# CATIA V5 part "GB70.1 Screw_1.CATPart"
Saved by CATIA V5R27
Part number: 螺钉_PowerCopy_1
Bounding box of the stored display mesh (mm): x -8 to 8, y -8 to 8, z -10 to 25
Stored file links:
  E:\资料\Catia超级副本\GB 70.1螺钉_带弹垫平垫\GB70.1 Screw_1.CATPart
  E:\资料\Catia超级副本\GB70.1 螺钉\DesignTable.xlsx
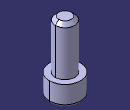
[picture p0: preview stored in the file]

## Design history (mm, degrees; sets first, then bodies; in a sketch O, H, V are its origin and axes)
Parameters
  `圆柱头直径` = 16 mm {design table}
  `圆柱头厚度` = 10 mm {design table}
  s = 8 mm {design table}
  t = 5 mm {design table}
  v = 1 mm {design table}
  b = 1.8 mm {design table}
  `公称直径` = 10 mm {design table}
  `螺钉长度` = 25 mm {design table}
AxisSystem1: origin (0, 0, 0), X (1, 0, 0), Y (0, 1, 0), Z (0, 0, 1)
Set1 "定位元素"
  Plane1: type Normal, Curve Line1, RefPoint Point1, Ratio 0
  Point1: (0, 0, 0), in AxisSystem1
Body1 (main body)
  Sketch1 on Plane1, origin (0, 0, 0), H (1, 0, 0), V (0, 1, 0)
    circle A1 centre (0, 0) radius 8
    radius A1 = 8 {= `圆柱头直径` /2}
  Pad1: profile Sketch1, direction (0, 0, -1), length 10 {= `圆柱头厚度`}
  Fillet1: radius 1 {= v}, on end face of Pad1
  Sketch2 on Plane1, origin (0, 0, 0), H (1, 0, 0), V (0, 1, 0)
    circle A1 centre (0, 0) radius 5
    radius A1 = 5 {= `公称直径` /2}
  Pad2: profile Sketch2, direction (0, 0, 1), length 25 {= `螺钉长度`}
  Chamfer1: length 1.8 {= b}, angle 45, on end face of Pad2
  Set2
    Line1: type PtDir, RefPoint Point1, Direction (0, 0, 1), Start 0, End 20
  Sketch3 on end face of Pad1, origin (0, 0, -10), H (1, 0, 0), V (0, -1, 0)
    point P1 (0, 0)
    point P2 (4, 0)
    construction circle A1 centre (0, 0) radius 4.6188
    construction circle A2 centre (0, 0) radius 4
    point P3 (4, -2.3094)
    point P4 (4, 2.3094)
    point P5 (0, 4.6188)
    point P6 (-4, 2.3094)
    point P7 (-4, -2.3094)
    point P8 (0, -4.6188)
    line L1 (4, -2.3094) -> (4, 2.3094)
    line L2 (4, 2.3094) -> (0, 4.6188)
    line L3 (0, 4.6188) -> (-4, 2.3094)
    line L4 (-4, 2.3094) -> (-4, -2.3094)
    line L5 (-4, -2.3094) -> (0, -4.6188)
    line L6 (0, -4.6188) -> (4, -2.3094)
    construction line L7 (0, 0) -> (4, 0)
    reference projected point E1 (0, 0) from axis of face of Pad1 from Sketch1.A1
    distance L1 L4 = 8 {= s}
    coincidence: A1 P3, A1 P4, A1 P5, A1 P6, A1 P7, A1 P8, P1 H, P1 E1
    tangency: A2 L1, A2 L2, A2 L3, A2 L4, A2 L5, A2 L6
    midpoint: P2 L1
    horizontal: L7 H
  Pocket1: profile Sketch3, direction (0, 0, 1), length 5 {= t}
Relations
  design table "GB70.1 螺钉参数表", configuration 86, drives `圆柱头直径`, `圆柱头厚度`, s, t, v, b, `公称直径`, `螺钉长度`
